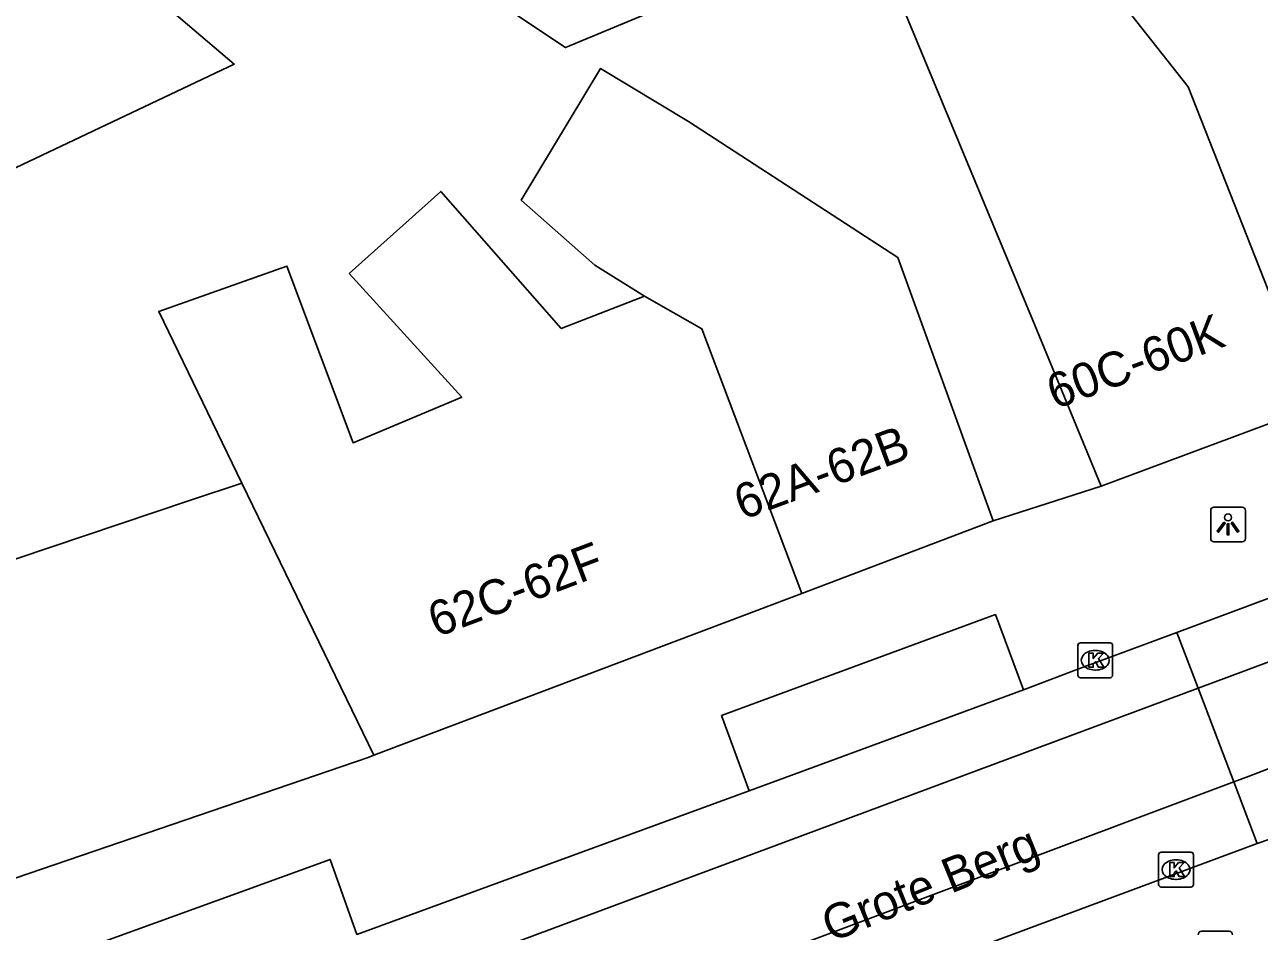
# Model space of a CAD drawing. Extents: x 160664 to 161506, y 382245 to 383288.
# Drawn here: x 161098.3 to 161133.75, y 382951.01 to 382977.05 of the extents above; entities that cross this region are included whole.
import ezdxf

# ---------------------------------------------------------------- set-up
doc = ezdxf.new("R2010")
doc.units = 0
for name, color, linetype in [('IMGEO_Afvalbak', 7, 'Continuous'), ('IMGEO_Kolk', 7, 'Continuous'), ('IMGEO_Lichtpunt', 7, 'Continuous'), ('IMGEO_Openbare_ruimte_label', 7, 'Continuous'), ('IMGEO_Pand', 7, 'Continuous'), ('IMGEO_Pand_nummerreeks', 7, 'Continuous'), ('IMGEO_Rijbaan_lokaal_gesloten', 7, 'Continuous'), ('IMGEO_Voetpad_open', 7, 'Continuous')]:
    doc.layers.add(name, color=color, linetype=linetype)

msp = doc.modelspace()

# ---------------------------------------------------------------- linework, layer by layer
at = {"layer": 'IMGEO_Afvalbak'}
for p, q in [((161132.088, 382951.011), (161132.878, 382951.011)), ((161132.878, 382951.011), (161132.088, 382951.011))]:
    msp.add_line(p, q, dxfattribs=at)
for centre, start, end in [((161132.088, 382950.911), 90, 180), ((161132.088, 382950.911), 90, 180), ((161132.878, 382950.911), 0, 90), ((161132.878, 382950.911), 360, 90)]:
    msp.add_arc(centre, 0.1, start, end, dxfattribs=at)
at = {"layer": 'IMGEO_Kolk'}
for p, q in [((161128.535, 382958.368), (161128.535, 382959.22)), ((161128.61, 382959.294), (161129.462, 382959.294)), ((161129.536, 382959.22), (161129.536, 382958.368)), ((161129.023, 382959.074), (161129.048, 382959.074)), ((161129.046, 382958.514), (161129.021, 382958.514)), ((161129.462, 382958.294), (161128.61, 382958.294)), ((161130.855, 382952.356), (161130.855, 382953.208)), ((161130.93, 382953.282), (161131.782, 382953.282)), ((161131.856, 382953.208), (161131.856, 382952.356)), ((161131.343, 382953.062), (161131.368, 382953.062)), ((161131.366, 382952.502), (161131.341, 382952.502)), ((161131.782, 382952.282), (161130.93, 382952.282))]:
    msp.add_line(p, q, dxfattribs=at)
for points in [[(161128.535, 382958.368), (161128.535, 382959.22)], [(161128.61, 382959.294), (161129.462, 382959.294)], [(161129.536, 382959.22), (161129.536, 382958.368)], [(161128.856, 382958.994), (161128.979, 382958.994), (161128.979, 382958.843), (161129.109, 382958.994), (161129.273, 382958.994), (161129.127, 382958.843), (161129.28, 382958.594), (161129.128, 382958.594), (161129.043, 382958.758), (161128.979, 382958.691), (161128.979, 382958.594), (161128.856, 382958.594), (161128.856, 382958.994)], [(161129.462, 382958.294), (161128.61, 382958.294)], [(161130.855, 382952.356), (161130.855, 382953.208)], [(161130.93, 382953.282), (161131.782, 382953.282)], [(161131.856, 382953.208), (161131.856, 382952.356)], [(161131.176, 382952.982), (161131.299, 382952.982), (161131.299, 382952.831), (161131.429, 382952.982), (161131.593, 382952.982), (161131.447, 382952.831), (161131.6, 382952.582), (161131.448, 382952.582), (161131.363, 382952.746), (161131.299, 382952.679), (161131.299, 382952.582), (161131.176, 382952.582), (161131.176, 382952.982)], [(161131.782, 382952.282), (161130.93, 382952.282)]]:
    msp.add_lwpolyline(points, dxfattribs=at)
for centre, start, end in [((161128.612, 382959.218), 91.552, 178.448), ((161128.612, 382959.218), 91.552, 178.448), ((161129.46, 382959.218), 1.552, 88.448), ((161129.46, 382959.218), 1.552, 88.448), ((161128.612, 382958.37), 181.552, 268.448), ((161128.612, 382958.37), 181.552, 268.448), ((161129.46, 382958.37), 271.552, 358.448), ((161129.46, 382958.37), 271.552, 358.448), ((161130.932, 382953.206), 91.552, 178.448), ((161130.932, 382953.206), 91.552, 178.448), ((161131.78, 382953.206), 1.552, 88.448), ((161131.78, 382953.206), 1.552, 88.448), ((161130.932, 382952.358), 181.552, 268.448), ((161130.932, 382952.358), 181.552, 268.448), ((161131.78, 382952.358), 271.552, 358.448), ((161131.78, 382952.358), 271.552, 358.448)]:
    msp.add_arc(centre, 0.0765, start, end, dxfattribs=at)
for centre, major_axis, ratio, start_param, end_param in [((161129.022, 382958.794), (-0.387, 0.002), 0.722429, 4.712389, 7.853982), ((161129.047, 382958.794), (-0.39, 0.002), 0.717154, 1.570796, 4.712389), ((161131.342, 382952.782), (-0.387, 0.002), 0.722429, 4.712389, 7.853982), ((161131.367, 382952.782), (-0.39, 0.002), 0.717154, 1.570796, 4.712389)]:
    msp.add_ellipse(centre, major_axis=major_axis, ratio=ratio, start_param=start_param, end_param=end_param, dxfattribs=at)
at = {"layer": 'IMGEO_Lichtpunt'}
for p, q in [((161133.253, 382963.193), (161132.445, 382963.193)), ((161133.253, 382963.193), (161132.445, 382963.193)), ((161132.351, 382963.098), (161132.351, 382962.291)), ((161132.351, 382963.098), (161132.351, 382962.291)), ((161133.347, 382962.291), (161133.347, 382963.098)), ((161133.347, 382962.291), (161133.347, 382963.098)), ((161132.445, 382962.197), (161133.253, 382962.197)), ((161132.445, 382962.197), (161133.253, 382962.197))]:
    msp.add_line(p, q, dxfattribs=at)
for points in [[(161132.725, 382962.762), (161132.764, 382962.734), (161132.576, 382962.472), (161132.538, 382962.499), (161132.725, 382962.762)], [(161132.827, 382962.714), (161132.874, 382962.714), (161132.874, 382962.392), (161132.827, 382962.392), (161132.827, 382962.714)], [(161132.937, 382962.734), (161132.975, 382962.761), (161133.162, 382962.499), (161133.123, 382962.471), (161132.937, 382962.734)]]:
    msp.add_lwpolyline(points, dxfattribs=at)
msp.add_circle((161132.85, 382962.896), 0.0994, dxfattribs=at)
for centre, start, end in [((161132.445, 382963.098), 90, 180), ((161132.445, 382963.098), 90, 180), ((161133.253, 382963.098), 0, 90), ((161133.253, 382963.098), 0, 90), ((161132.445, 382962.291), 180, 270), ((161132.445, 382962.291), 180, 270), ((161133.253, 382962.291), 270, 0), ((161133.253, 382962.291), 270, 360)]:
    msp.add_arc(centre, 0.0946, start, end, dxfattribs=at)
at = {"layer": 'IMGEO_Pand'}
for points in [[(161124.191, 382984.784), (161110.303, 382978.748), (161113.83, 382976.389), (161120.744, 382979.272), (161121.184, 382978.209), (161122.938, 382978.941), (161127.298, 382968.415), (161129.211, 382963.795)], [(161124.191, 382984.784), (161131.708, 382975.266), (161135.325, 382966.07)], [(161092.735, 382977.235), (161094.742, 382971.374), (161104.322, 382975.914), (161097.867, 382981.406)], [(161116.095, 382969.253), (161114.672, 382970.145), (161112.557, 382972.008), (161114.832, 382975.786), (161117.359, 382974.264), (161123.369, 382970.359), (161126.109, 382962.795)], [(161104.537, 382963.884), (161102.151, 382968.811), (161105.832, 382970.116), (161107.732, 382965.041), (161110.852, 382966.351), (161107.621, 382969.898), (161110.247, 382972.258), (161113.708, 382968.321), (161116.095, 382969.253)], [(161120.614, 382960.716), (161117.746, 382968.316), (161116.095, 382969.253)], [(161135.325, 382966.07), (161129.211, 382963.795)], [(161097.669, 382952.41), (161095.664, 382958.267), (161094.879, 382957.999), (161094.069, 382960.365), (161103.031, 382963.378), (161104.537, 382963.884)], [(161108.324, 382956.065), (161104.537, 382963.884)], [(161126.109, 382962.795), (161120.614, 382960.716)], [(161120.614, 382960.716), (161108.324, 382956.065)], [(161108.324, 382956.065), (161108.16, 382956.003), (161097.669, 382952.41)]]:
    msp.add_lwpolyline(points, dxfattribs=at)
at = {"layer": 'IMGEO_Rijbaan_lokaal_gesloten'}
for points in [[(161131.99, 382957.995), (161148.412, 382964.113), (161156.081, 382967.198)], [(161157.124, 382964.597), (161154.805, 382963.673), (161133.457, 382955.47), (161133.011, 382955.303)], [(161157.832, 382962.832), (161146.471, 382958.343), (161134.046, 382953.655), (161133.682, 382953.531)], [(161131.383, 382959.595), (161135.104, 382960.976)], [(161126.973, 382957.945), (161128.533, 382958.538), (161131.383, 382959.595)], [(161131.383, 382959.595), (161131.99, 382957.995)], [(161131.99, 382957.995), (161098.89, 382945.662), (161080.422, 382939.64)], [(161119.104, 382955.049), (161121.778, 382956.03), (161126.973, 382957.945)], [(161133.011, 382955.303), (161131.99, 382957.995)], [(161100.365, 382943.182), (161101.826, 382943.714), (161112.429, 382947.575), (161133.011, 382955.303)], [(161107.841, 382950.917), (161119.104, 382955.049)], [(161133.682, 382953.531), (161133.011, 382955.303)], [(161133.682, 382953.531), (161110.287, 382944.833)]]:
    msp.add_lwpolyline(points, dxfattribs=at)
at = {"layer": 'IMGEO_Voetpad_open'}
for points in [[(161129.211, 382963.795), (161126.109, 382962.795)], [(161119.104, 382955.049), (161118.308, 382957.204), (161121.008, 382958.201), (161126.169, 382960.107), (161126.973, 382957.945)], [(161099.951, 382948.027), (161099.178, 382950.212), (161104.384, 382952.098), (161107.076, 382953.073), (161107.841, 382950.917)]]:
    msp.add_lwpolyline(points, dxfattribs=at)

# ---------------------------------------------------------------- texts
at = {"layer": 'IMGEO_Openbare_ruimte_label'}
msp.add_text('Grote Berg', height=1, rotation=22.1526, dxfattribs=at).set_placement((161121.45, 382950.684))
at = {"layer": 'IMGEO_Pand_nummerreeks'}
for s, rotation, p in [('60C-60K', 20.4088, (161127.884, 382965.99)), ('62A-62B', 20.3441, (161118.91, 382962.814)), ('62C-62F', 20.7296, (161110.127, 382959.443))]:
    msp.add_text(s, height=1, rotation=rotation, dxfattribs=at).set_placement(p)

doc.saveas('drawing.dxf')
